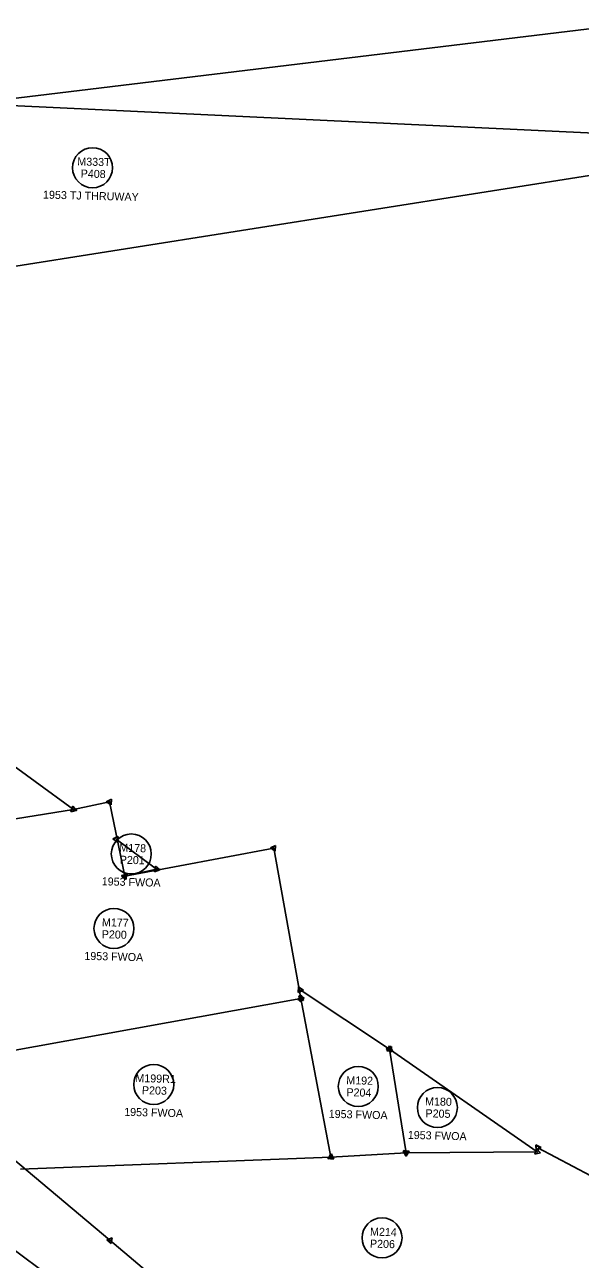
# Model space of a CAD drawing. Extents: x 325018 to 414989, y 1517547 to 1550415.
# Drawn here: x 364226 to 364591, y 1523754 to 1524563 of the extents above; entities that cross this region are included whole.
import ezdxf

# ---------------------------------------------------------------- set-up
doc = ezdxf.new("R2010")
doc.units = 0
for name, color, linetype in [('Level 56', 7, 'Continuous'), ('MEE', 7, 'Continuous'), ('MHB', 7, 'Continuous'), ('MHBWOA', 7, 'Continuous'), ('MRBL1', 7, 'Continuous'), ('MRBL2', 7, 'Continuous')]:
    doc.layers.add(name, color=color, linetype=linetype)

msp = doc.modelspace()

# ---------------------------------------------------------------- linework, layer by layer
at = {"layer": 'Level 56'}
for centre in [(364270.53, 1524469.65), (364295.98, 1524019.75), (364284.56, 1523970.89), (364310.7, 1523868.61), (364444.94, 1523867.31), (364496.84, 1523853.48), (364460.51, 1523768.03)]:
    msp.add_circle(centre, 13.12, dxfattribs=at)
at = {"layer": 'MEE'}
for p, q in [((364823.89, 1523688.76), (364562.7, 1523827.12)), ((364151, 1523811.11), (364334.73, 1523673.81))]:
    msp.add_line(p, q, dxfattribs=at)
for points in [[(364561.68, 1523825.2), (364561.54, 1523828.97)], [(364561.54, 1523828.97), (364564.88, 1523827.2)], [(364564.88, 1523827.2), (364561.68, 1523825.2)]]:
    msp.add_lwpolyline(points, dxfattribs=at)
msp.add_circle((364562.7, 1523827.12), 1.09, dxfattribs=at)
at = {"layer": 'MHB'}
for p, q in [((364094.47, 1524500.15), (364618.27, 1524563.46)), ((364776.1, 1524492.9), (364204.15, 1524402.72))]:
    msp.add_line(p, q, dxfattribs=at)
at = {"layer": 'MHBWOA'}
for p, q in [((364201.2, 1524090.18), (364258.03, 1524048.99)), ((364258.03, 1524048.99), (364281.73, 1524053.9)), ((364281.73, 1524053.9), (364291.66, 1524005.08)), ((364182.44, 1524036.73), (364258.03, 1524048.99)), ((364285.99, 1524029.43), (364312.55, 1524009.74)), ((364291.66, 1524005.08), (364389.43, 1524023.54)), ((364389.43, 1524023.54), (364407.24, 1523925.01)), ((364312.55, 1524009.74), (364291.66, 1524005.08)), ((364407.24, 1523925.01), (364210.19, 1523889.38)), ((364465.5, 1523891.76), (364406.75, 1523930.64)), ((364407.24, 1523925.01), (364426.95, 1523820.97)), ((364465.5, 1523891.76), (364562.39, 1523824.4)), ((364476.39, 1523823.86), (364465.5, 1523891.76)), ((364426.95, 1523820.97), (364223.22, 1523813.15)), ((364426.95, 1523820.97), (364476.39, 1523823.86)), ((364562.39, 1523824.4), (364476.39, 1523823.86))]:
    msp.add_line(p, q, dxfattribs=at)
for points in [[(364279.55, 1524054.02), (364282.93, 1524055.72)], [(364282.71, 1524051.94), (364279.55, 1524054.02)], [(364282.93, 1524055.72), (364282.71, 1524051.94)], [(364256.37, 1524047.57), (364257.63, 1524051.13)], [(364260.08, 1524048.26), (364256.37, 1524047.57)], [(364256.53, 1524047.41), (364257.4, 1524051.08)], [(364260.14, 1524048.49), (364256.53, 1524047.41)], [(364257.4, 1524051.08), (364260.14, 1524048.49)], [(364257.63, 1524051.13), (364260.08, 1524048.26)], [(364283.82, 1524029.67), (364287.29, 1524031.18)], [(364286.86, 1524027.42), (364283.82, 1524029.67)], [(364287.29, 1524031.18), (364286.86, 1524027.42)], [(364387.25, 1524023.71), (364390.66, 1524025.33)], [(364390.36, 1524021.56), (364387.25, 1524023.71)], [(364390.66, 1524025.33), (364390.36, 1524021.56)], [(364289.49, 1524005.22), (364292.88, 1524006.89)], [(364292.62, 1524003.12), (364289.49, 1524005.22)], [(364289.58, 1524005.73), (364293.27, 1524006.56)], [(364292.14, 1524002.95), (364289.58, 1524005.73)], [(364293.27, 1524006.56), (364292.14, 1524002.95)], [(364292.88, 1524006.89), (364292.62, 1524003.12)], [(364311.09, 1524008.12), (364311.87, 1524011.81)], [(364314.68, 1524009.29), (364311.09, 1524008.12)], [(364311.87, 1524011.81), (364314.68, 1524009.29)], [(364405.55, 1523928.83), (364405.78, 1523932.6)], [(364405.78, 1523932.6), (364408.93, 1523930.51)], [(364405.26, 1523924.08), (364407.42, 1523927.18)], [(364409.03, 1523923.77), (364405.26, 1523924.08)], [(364408.93, 1523930.51), (364405.55, 1523928.83)], [(364405.81, 1523926.66), (364409.38, 1523925.41)], [(364406.52, 1523922.95), (364405.81, 1523926.66)], [(364409.38, 1523925.41), (364406.52, 1523922.95)], [(364407.42, 1523927.18), (364409.03, 1523923.77)], [(364463.33, 1523891.94), (364466.74, 1523893.54)], [(364466.43, 1523889.78), (364463.33, 1523891.94)], [(364463.67, 1523890.58), (364465.4, 1523893.94)], [(364465.4, 1523893.94), (364467.44, 1523890.76)], [(364466.74, 1523893.54), (364466.43, 1523889.78)], [(364467.44, 1523890.76), (364463.67, 1523890.58)], [(364424.92, 1523820.17), (364427.28, 1523823.13)], [(364428.66, 1523819.61), (364424.92, 1523820.17)], [(364425.13, 1523819.77), (364426.83, 1523823.14)], [(364428.9, 1523819.99), (364425.13, 1523819.77)], [(364426.83, 1523823.14), (364428.9, 1523819.99)], [(364427.28, 1523823.13), (364428.66, 1523819.61)], [(364474.49, 1523824.94), (364478.27, 1523824.96)], [(364476.4, 1523821.68), (364474.49, 1523824.94)], [(364476.06, 1523821.7), (364474.69, 1523825.22)], [(364474.69, 1523825.22), (364478.42, 1523824.64)], [(364478.42, 1523824.64), (364476.06, 1523821.7)], [(364478.27, 1523824.96), (364476.4, 1523821.68)], [(364560.78, 1523822.92), (364561.9, 1523826.53)], [(364564.47, 1523823.75), (364560.78, 1523822.92)], [(364561.9, 1523826.53), (364564.47, 1523823.75)]]:
    msp.add_lwpolyline(points, dxfattribs=at)
for centre, radius in [((364281.73, 1524053.9), 0.227), ((364258.03, 1524048.99), 0.227), ((364258.03, 1524048.99), 0.227), ((364285.99, 1524029.42), 1.09), ((364389.43, 1524023.54), 0.227), ((364291.66, 1524005.08), 1.09), ((364291.66, 1524005.08), 0.227), ((364312.55, 1524009.74), 0.227), ((364406.75, 1523930.64), 1.09), ((364407.24, 1523925.01), 1.09), ((364407.24, 1523925.01), 0.227), ((364465.5, 1523891.76), 1.09), ((364465.5, 1523891.76), 0.227), ((364426.96, 1523820.97), 1.09), ((364426.95, 1523820.97), 0.227), ((364476.39, 1523823.86), 1.09), ((364476.39, 1523823.86), 0.227), ((364562.39, 1523824.4), 0.227)]:
    msp.add_circle(centre, radius, dxfattribs=at)
at = {"layer": 'MRBL1'}
msp.add_line((364150.79, 1524513.55), (365471, 1524450.93), dxfattribs=at)
at = {"layer": 'MRBL2'}
for p, q in [((363809.01, 1524163.56), (364281.98, 1523766.42)), ((364281.98, 1523766.42), (364791.44, 1523338.64))]:
    msp.add_line(p, q, dxfattribs=at)
for points in [[(364279.83, 1523766.8), (364283.38, 1523768.09)], [(364282.72, 1523764.37), (364279.83, 1523766.8)], [(364283.38, 1523768.09), (364282.72, 1523764.37)]]:
    msp.add_lwpolyline(points, dxfattribs=at)
msp.add_circle((364281.98, 1523766.42), 0.227, dxfattribs=at)

# ---------------------------------------------------------------- texts
at = {"layer": 'Level 56'}
for s, height, p in [('M333T', 5.249, (364260.49, 1524471.22)), ('P408', 5.249, (364262.69, 1524463.29)), ('1953 TJ THRUWAY', 5.2493, (364237.99, 1524449.47)), ('M178', 5.249, (364288.05, 1524021.27)), ('P201', 5.249, (364288.32, 1524013.38)), ('1953 FWOA', 5.249, (364276.53, 1523999.23)), ('M177', 5.249, (364276.63, 1523972.4)), ('P200', 5.249, (364276.53, 1523964.53)), ('1953 FWOA', 5.249, (364265.11, 1523950.37)), ('M199R1', 5.249, (364298.59, 1523870.24)), ('P203', 5.249, (364302.88, 1523862.25)), ('M192', 5.249, (364437.01, 1523868.83)), ('P204', 5.249, (364437.1, 1523860.95)), ('M180', 5.249, (364488.72, 1523855.01)), ('1953 FWOA', 5.249, (364291.25, 1523848.09)), ('1953 FWOA', 5.249, (364425.5, 1523846.79)), ('P205', 5.249, (364489, 1523847.12)), ('1953 FWOA', 5.249, (364477.39, 1523832.97)), ('M214', 5.249, (364452.58, 1523769.55)), ('P206', 5.249, (364452.55, 1523761.68))]:
    msp.add_text(s, height=height, rotation=358.51411, dxfattribs=at).set_placement(p)

doc.saveas('drawing.dxf')
